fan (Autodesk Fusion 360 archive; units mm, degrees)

design "fan" references "Fan BFB1012 97x94x33"
sketch "Sketch1" plane through (0, 0, 0) normal (1, 0, 0) x axis (0, 0, -1)
sketch "Sketch2" plane through (0, 0, 0) normal (1, 0, 0) x axis (0, 0, -1)
  line L1 (-76.7953, 5.9701) -> (10.7047, 5.9701)
  line L2 (-76.7953, 30.4701) -> (-76.7953, 5.9701)
  line L3 (10.7047, 30.4701) -> (-76.7953, 30.4701)
  line L4 (10.7047, 5.9701) -> (10.7047, 30.4701)
  line L5 (-76.7953, 5.9701) -> (10.7047, 30.4701)
  line L6 (-79.5453, 30.4701) -> (13.4547, 30.4701)
  line L7 (-79.5453, 5.9701) -> (-79.5453, 30.4701)
  line L8 (13.4547, 5.9701) -> (-79.5453, 5.9701)
  line L9 (13.4547, 30.4701) -> (13.4547, 5.9701)
  line L10 (-79.5453, 5.9701) -> (13.4547, 30.4701)
  line L11 (13.4547, 5.9701) -> (-79.5453, 30.4701)
  point P10 (-33.0453, 18.2201)
  point P2 (10.7047, 5.9701)
  point P3 (-76.7953, 5.9701)
  point P5 (10.7047, 30.4701)
  point P8 (-79.5453, 5.9701)
  point P9 (13.4547, 5.9701)
  point P7 (-79.5453, 30.4701)
  horizontal L1
  vertical L2
  horizontal L3
  vertical L4
  horizontal L6
  perpendicular L6 L7
  parallel L6 L8
  parallel L7 L9
  coincident L10 P10
  coincident L11 P10
  midpoint L5 P10
  dimension "d1" distance P2 P3 = 87.5
  dimension "d2" distance P2 P5 = 24.5
  dimension "d3" distance P8 P9 = 93
  dimension "d4" distance P7 P8 = 24.5
canvas "Canvas2" sketch "Sketch2"
work_plane "WorkPlane1" sketch "Sketch2" AlongDistance -5.5
sketch "Sketch3" plane through (-5.5, 0, 0) normal (1, 0, 0) x axis (0, 0, -1)
  line L1 (13.4547, 30.4701) -> (13.4547, 5.9701)
  line L2 (-79.5453, 5.9701) -> (-79.5453, 30.4701)
  line L3 (-76.7953, 5.9701) -> (10.7047, 5.9701)
  line L4 (10.7047, 30.4701) -> (-76.7953, 30.4701)
  line L5 (-79.5453, 30.4701) -> (13.4547, 30.4701)
  line L6 (13.4547, 5.9701) -> (-79.5453, 5.9701)
loft "Loft1" sketch "Sketch2" + "Sketch3"
sketch "Sketch4" plane through (0, 0, 0) normal (1, 0, 0) x axis (0, 0, -1)
  line L1 (-76.7953, 30.4701) -> (10.7047, 30.4701)
  line L2 (-76.7953, 5.9701) -> (-76.7953, 30.4701)
  line L3 (10.7047, 5.9701) -> (-76.7953, 5.9701)
  line L4 (10.7047, 30.4701) -> (10.7047, 5.9701)
  line L5 (1.7047, 30.4701) -> (10.7047, 30.4701)
  line L6 (-16.2953, 30.4701) -> (1.7047, 30.4701)
  line L7 (-16.2953, 26.9701) -> (-16.2953, 30.4701)
  line L8 (1.7047, 26.9701) -> (-16.2953, 26.9701)
  line L9 (1.7047, 30.4701) -> (1.7047, 26.9701)
  point P2 (10.7047, 30.4701)
  point P6 (10.7047, 30.4701)
  point P7 (1.7047, 30.4701)
  point P8 (-16.2953, 30.4701)
  point P10 (1.7047, 26.9701)
  coincident P2 P6
  perpendicular L4 L5
  horizontal L6
  vertical L7
  horizontal L8
  vertical L9
  dimension "d6" distance P6 P7 = 9
  dimension "d7" distance P7 P8 = 18
  dimension "d8" distance P7 P10 = 3.5
shell "Shell1" innerThickness 2
extrude "Extrude1" cut of existing geometry blind -2
sketch "Sketch5" plane through (-5.5, 0, 0) normal (-1, 0, 0) x axis (0, 0, 1)
  line L1 (77.3092, 28.4701) -> (-11.2186, 28.4701)
  line L2 (77.3092, 7.9701) -> (77.3092, 28.4701)
  line L3 (-11.2186, 7.9701) -> (77.3092, 7.9701)
  line L4 (-11.2186, 28.4701) -> (-11.2186, 7.9701)
  line L5 (-13.4547, 30.4701) -> (79.5453, 30.4701)
  line L6 (-13.4547, 5.9701) -> (-13.4547, 30.4701)
  line L7 (79.5453, 5.9701) -> (-13.4547, 5.9701)
  line L8 (79.5453, 30.4701) -> (79.5453, 5.9701)
  line L9 (79.5453, 30.4701) -> (-13.4547, 5.9701)
  line L10 (-15.1047, 1.4701) -> (81.1953, 1.4701)
  line L11 (-15.1047, 34.9701) -> (-15.1047, 1.4701)
  line L12 (81.1953, 34.9701) -> (-15.1047, 34.9701)
  line L13 (81.1953, 1.4701) -> (81.1953, 34.9701)
  line L14 (-15.1047, 34.9701) -> (81.1953, 1.4701)
  line L15 (81.1953, 34.9701) -> (-15.1047, 1.4701)
  line L16 (-1.7047, 26.9701) -> (16.2953, 26.9701)
  line L17 (-1.7047, 30.4701) -> (-1.7047, 26.9701)
  line L18 (16.2953, 26.9701) -> (16.2953, 30.4701)
  line L19 (16.2953, 30.4701) -> (-1.7047, 30.4701)
  line L20 (-1.7047, 35.4701) -> (16.2953, 35.4701)
  line L21 (-1.7047, 25.4701) -> (-1.7047, 35.4701)
  line L22 (16.2953, 25.4701) -> (-1.7047, 25.4701)
  line L23 (16.2953, 35.4701) -> (16.2953, 25.4701)
  line L24 (-1.7047, 25.4701) -> (16.2953, 35.4701)
  line L25 (16.2953, 25.4701) -> (-1.7047, 35.4701)
  line L26 (18.2953, 37.4701) -> (18.2953, 23.4701)
  line L27 (-3.7047, 37.4701) -> (18.2953, 37.4701)
  line L28 (-3.7047, 23.4701) -> (-3.7047, 37.4701)
  line L29 (18.2953, 23.4701) -> (-3.7047, 23.4701)
  point P8 (-13.4547, 5.9701)
  point P10 (-13.4547, 5.9701)
  point P6 (79.5453, 30.4701)
  point P11 (79.5453, 30.4701)
  point P16 (33.0453, 18.2201)
  point P19 (-1.7047, 30.4701)
  point P21 (-1.7047, 30.4701)
  point P20 (16.2953, 30.4701)
  point P22 (16.2953, 30.4701)
  point P27 (7.2953, 30.4701)
  point P14 (-15.1047, 34.9701)
  point P15 (81.1953, 34.9701)
  point P13 (-15.1047, 1.4701)
  point P25 (-1.7047, 25.4701)
  point P26 (16.2953, 25.4701)
  point P24 (-1.7047, 35.4701)
  point P12 (81.1953, 1.4701)
  coincident P8 P10
  coincident P6 P11
  horizontal L10
  perpendicular L10 L11
  parallel L10 L12
  parallel L11 L13
  coincident L14 P16
  coincident L15 P16
  midpoint L9 P16
  coincident P19 P21
  coincident P20 P22
  horizontal L20
  perpendicular L20 L21
  parallel L20 L22
  parallel L21 L23
  coincident L24 P27
  coincident L25 P27
  midpoint L19 P27
  dimension "d12" distance P14 P15 = 96.3
  dimension "d13" distance P13 P14 = 33.5
  dimension "d14" distance P25 P26 = 18
  dimension "d15" distance P24 P25 = 10
  dimension "d17" = 2
  dimension "d26" distance P12 P13 = 96.3
extrude "Extrude2" add sketch "Sketch5" profile of L1 L17 L18 L21 L22 L23 L26 L28 L29 against normal blind 5.5
extrude "Extrude3" cut sketch "Sketch5" profile of L1 L5 L17 L18 L21 L23 against normal blind 5.5
extrude "Extrude4" new body sketch "Sketch5" profile of L1 L5 L6 L7 L8 L10 L11 L12 L13 L17 L18 L21 L22 L23 L26 L28 L29 along normal blind 9
extrude "Extrude5" add of existing geometry blind 2
sketch "Sketch6" plane through (-14.5, 0, 0) normal (-1, 0, 0) x axis (0, 0, 1)
  line L1 (-3.7047, 30.4701) -> (-13.4547, 30.4701)
  line L2 (-3.7047, 23.4701) -> (-3.7047, 30.4701)
  line L3 (18.2953, 23.4701) -> (-3.7047, 23.4701)
  line L4 (18.2953, 30.4701) -> (18.2953, 23.4701)
  line L5 (79.5453, 30.4701) -> (18.2953, 30.4701)
  line L6 (79.5453, 5.9701) -> (79.5453, 30.4701)
  line L7 (-13.4547, 5.9701) -> (79.5453, 5.9701)
  line L8 (-13.4547, 30.4701) -> (-13.4547, 5.9701)
  line L9 (-1.7047, 25.4701) -> (16.2953, 25.4701)
  line L10 (-1.7047, 34.9701) -> (-1.7047, 25.4701)
  line L11 (-15.1047, 34.9701) -> (-1.7047, 34.9701)
  line L12 (-15.1047, 1.4701) -> (-15.1047, 34.9701)
  line L13 (81.1953, 1.4701) -> (-15.1047, 1.4701)
  line L14 (81.1953, 36.9701) -> (81.1953, 1.4701)
  line L15 (16.2953, 36.9701) -> (81.1953, 36.9701)
  line L16 (16.2953, 25.4701) -> (16.2953, 36.9701)
  line L17 (73.1953, 36.9701) -> (81.1953, 36.9701)
  line L18 (55.1953, 33.4701) -> (73.1953, 33.4701)
  line L19 (29, 33.4701) -> (73.1953, 33.4701)
  circle C1 centre (73.1953, 33.4701) radius 2
  circle C2 centre (55.1953, 33.4701) radius 2
  circle C3 centre (45.1953, 33.4701) radius 2
  circle C4 centre (37.1953, 33.4701) radius 2
  point P16 (81.1953, 36.9701)
  point P18 (81.1953, 36.9701)
  point P19 (73.1953, 36.9701)
  point P20 (73.1953, 33.4701)
  point P21 (73.1953, 33.4701)
  point P22 (55.1953, 33.4701)
  point P23 (55.1953, 33.4701)
  point P24 (73.1953, 33.4701)
  point P26 (45.1953, 33.4701)
  point P27 (37.1953, 33.4701)
  coincident P16 P18
  coincident L15 P19
  coincident P20 P21
  horizontal L18
  coincident P22 P23
  coincident P20 P24
  coincident L19 P26
  coincident L19 P27
  dimension "d27" distance P18 P19 = 8
  dimension "d28" diameter C1 = 4
  dimension "d30" distance L5 P20 = 3
  dimension "d31" distance P21 P22 = 18
  dimension "d32" diameter C2 = 4
  dimension "d33" diameter C3 = 4
  dimension "d34" distance P23 P26 = 10
  dimension "d35" diameter C4 = 4
  dimension "d36" distance P26 P27 = 8
extrude "Extrude6" cut sketch "Sketch6" profile of C1 C2 C3 C4 against normal blind 9
work_plane "WorkPlane2" AlongDistance 10
sketch "Sketch7" plane through (-24.5, 0, 0) normal (-1, 0, 0) x axis (0, 0, 1)
component_insert "Component Insert"
position "Position1"
work_plane "WorkPlane3" AlongDistance 0
sketch "Sketch8" plane through (-14.5, 0, 0) normal (-1, 0, 0) x axis (0, 0, 1)
  line L1 (81.1953, 34.9701) -> (-15.1047, 34.9701)
  line L2 (81.1953, 1.4701) -> (81.1953, 34.9701)
  line L3 (-15.1047, 1.4701) -> (81.1953, 1.4701)
  line L4 (-15.1047, 34.9701) -> (-15.1047, 1.4701)
  line L5 (81.1953, 1.4701) -> (-15.1047, 34.9701)
  line L6 (-15.1047, 2.0928) -> (81.1953, 34.9701)
  point P3 (81.1953, 1.4701)
  point P6 (81.1953, 1.4701)
  point P2 (-15.1047, 34.9701)
  point P4 (-15.1047, 34.9701)
  point P8 (-15.1047, 34.9701)
  point P9 (81.1953, 1.4701)
  point P10 (-15.1047, 2.0928)
  horizontal L1
  vertical L2
  horizontal L3
  vertical L4
  coincident P3 P6
  coincident P2 P4
  coincident P2 P8
  coincident P3 P9
  coincident L4 P10
joint "Assemble1" alignAngle 90 alignOffsetX 0 alignOffsetY 0 alignOffsetZ 30
sketch "Sketch9" plane through (-44.5, 0, 0) normal (1, 0, 0) x axis (0, 1, 0)
  line L1 (1.7701, 4.0953) -> (1.7701, 61.9953)
  line L2 (34.6701, 4.0953) -> (1.7701, 4.0953)
  line L3 (34.6701, 61.9953) -> (34.6701, 4.0953)
  line L4 (1.7701, 61.9953) -> (34.6701, 61.9953)
  line L5 (36.6701, 63.9953) -> (36.6701, 2.0953)
  line L6 (-0.2299, 63.9953) -> (36.6701, 63.9953)
  line L7 (-0.2299, 2.0953) -> (-0.2299, 63.9953)
  line L8 (36.6701, 2.0953) -> (-0.2299, 2.0953)
  dimension "d47" = 2
extrude "Extrude8" new body sketch "Sketch9" against normal blind 10
sketch "Sketch11" plane through (0, 1.4701, 0) normal (0, -1, 0) x axis (1, 0, 0)
  line L1 (-5.5, 81.1953) -> (-5.5, -15.1047)
  line L2 (-14.5, 81.1953) -> (-5.5, 81.1953)
  line L3 (-14.5, -15.1047) -> (-14.5, 81.1953)
  line L4 (-5.5, -15.1047) -> (-14.5, -15.1047)
  line L5 (-44.5, 63.9953) -> (-44.5, 2.0953)
  line L6 (-54.5, 63.9953) -> (-44.5, 63.9953)
  line L7 (-54.5, 2.0953) -> (-54.5, 63.9953)
  line L8 (-44.5, 2.0953) -> (-54.5, 2.0953)
sketch "Sketch12" plane through (-14.5, 0, 0) normal (-1, 0, 0) x axis (0, 0, 1)
  line L1 (-13.4547, 5.9701) -> (79.5453, 5.9701)
  line L2 (-3.7047, 30.4701) -> (-13.4547, 30.4701)
  line L3 (-3.7047, 23.4701) -> (-3.7047, 30.4701)
  line L4 (18.2953, 23.4701) -> (-3.7047, 23.4701)
  line L5 (18.2953, 30.4701) -> (18.2953, 23.4701)
  line L6 (79.5453, 30.4701) -> (18.2953, 30.4701)
  line L7 (79.5453, 5.9701) -> (79.5453, 30.4701)
  line L8 (-13.4547, 5.9701) -> (79.5453, 5.9701)
  line L9 (-13.4547, 30.4701) -> (-13.4547, 5.9701)
  line L10 (-1.7047, 25.4701) -> (16.2953, 25.4701)
  line L11 (-1.7047, 34.9701) -> (-1.7047, 25.4701)
  line L12 (-15.1047, 34.9701) -> (-1.7047, 34.9701)
  line L13 (-15.1047, 1.4701) -> (-15.1047, 34.9701)
  line L14 (81.1953, 1.4701) -> (-15.1047, 1.4701)
  line L15 (81.1953, 36.9701) -> (81.1953, 1.4701)
  line L16 (16.2953, 36.9701) -> (81.1953, 36.9701)
  line L17 (16.2953, 25.4701) -> (16.2953, 36.9701)
  line L18 (-15.1047, 5.9701) -> (-13.4547, 5.9701)
  line L19 (81.1953, 5.9701) -> (79.5453, 5.9701)
  line L20 (-3.7047, 25.4701) -> (-1.7047, 25.4701)
  line L21 (18.2953, 25.4701) -> (16.2953, 25.4701)
  line L22 (18.2953, 36.9701) -> (18.2953, 30.4701)
  line L23 (-3.7047, 34.9701) -> (-3.7047, 30.4701)
  line L24 (81.1953, 30.4701) -> (79.5453, 30.4701)
  line L25 (18, 30.4701) -> (18.2953, 30.4701)
  line L26 (16.2953, 30.4701) -> (18, 30.4701)
  circle C1 centre (45.1953, 33.4701) radius 2
  circle C2 centre (55.1953, 33.4701) radius 2
  circle C3 centre (37.1953, 33.4701) radius 2
  circle C4 centre (73.1953, 33.4701) radius 2
  point P15 (-13.4547, 5.9701)
  point P24 (-13.4547, 5.9701)
  point P25 (-15.1047, 5.9701)
  point P14 (79.5453, 5.9701)
  point P26 (79.5453, 5.9701)
  point P27 (81.1953, 5.9701)
  point P17 (-1.7047, 25.4701)
  point P28 (-1.7047, 25.4701)
  point P29 (-3.7047, 25.4701)
  point P16 (16.2953, 25.4701)
  point P30 (16.2953, 25.4701)
  point P31 (18.2953, 25.4701)
  point P12 (18.2953, 30.4701)
  point P32 (18.2953, 30.4701)
  point P33 (18.2953, 36.9701)
  point P9 (-3.7047, 30.4701)
  point P34 (-3.7047, 30.4701)
  point P35 (-3.7047, 34.9701)
  point P13 (79.5453, 30.4701)
  point P36 (79.5453, 30.4701)
  point P37 (81.1953, 30.4701)
  point P39 (16.2953, 30.4701)
  coincident P15 P24
  coincident L13 P25
  perpendicular L13 L18
  coincident P14 P26
  coincident L15 P27
  perpendicular L15 L19
  coincident P17 P28
  coincident L3 P29
  perpendicular L3 L20
  coincident P16 P30
  coincident L5 P31
  perpendicular L5 L21
  coincident P12 P32
  coincident L16 P33
  perpendicular L16 L22
  coincident P9 P34
  coincident L12 P35
  perpendicular L12 L23
  coincident P13 P36
  coincident L15 P37
  perpendicular L15 L24
  perpendicular L22 L25
  coincident L17 P39
  perpendicular L17 L26
extrude "Extrude9" add sketch "Sketch12" profile of L1 L2 L7 L8 L9 L12 L13 L14 L15 L18 L19 L23 L24 along normal blind 30
sketch "Sketch13" plane through (0, 5.9701, 0) normal (0, 1, 0) x axis (-1, 0, 0)
  line L1 (5.5, -13.4547) -> (5.5, 79.5453)
  line L2 (44.5, -13.4547) -> (5.5, -13.4547)
  line L3 (44.5, 2.0953) -> (44.5, -13.4547)
  line L4 (44.5, 4.0953) -> (44.5, 2.0953)
  line L5 (44.5, 61.9953) -> (44.5, 4.0953)
  line L6 (44.5, 63.9953) -> (44.5, 61.9953)
  line L7 (44.5, 79.5453) -> (44.5, 63.9953)
  line L8 (5.5, 79.5453) -> (44.5, 79.5453)
  line L9 (5.5, 77.3092) -> (2, 75.5592)
  line L10 (44.5, 61.9953) -> (5.5, 77.3092)
  line L11 (5.5, -11.3215) -> (44.5, 4.0953)
  point P11 (5.5, 77.3092)
  point P12 (5.5, 77.3092)
  point P7 (44.5, 61.9953)
  point P13 (44.5, 61.9953)
  point P6 (44.5, 4.0953)
  point P14 (44.5, 4.0953)
  point P15 (5.5, -11.3215)
  coincident P11 P12
  coincident P7 P13
  coincident P6 P14
  coincident L1 P15
extrude "Extrude10" add sketch "Sketch13" profile of L1 L2 L3 L4 L6 L7 L8 L10 L11 along normal blind 25
work_plane "WorkPlane4"
revolve "Revolve1" AlongAngle -6
extrude "Extrude11" cut of existing geometry blind -1
sketch "Sketch14" plane through (-14.5, 0, 0) normal (-1, 0, 0) x axis (0, 0, 1)
  line L1 (79.5453, 30.4701) -> (79.5453, 30.9701)
  line L2 (81.1953, 30.4701) -> (79.5453, 30.4701)
  line L3 (81.1953, 36.9701) -> (81.1953, 30.4701)
  line L4 (16.2953, 36.9701) -> (81.1953, 36.9701)
  line L5 (16.2953, 25.4701) -> (16.2953, 36.9701)
  line L6 (-1.7047, 25.4701) -> (16.2953, 25.4701)
  line L7 (-1.7047, 34.9701) -> (-1.7047, 25.4701)
  line L8 (-3.7047, 34.9701) -> (-1.7047, 34.9701)
  line L9 (-3.7047, 30.4701) -> (-3.7047, 34.9701)
  line L10 (-3.7047, 23.4701) -> (-3.7047, 30.4701)
  line L11 (18.2953, 23.4701) -> (-3.7047, 23.4701)
  line L12 (18.2953, 30.4701) -> (18.2953, 23.4701)
  line L13 (73.7752, 30.4701) -> (18.2953, 30.4701)
  line L14 (73.7752, 30.9701) -> (73.7752, 30.4701)
  line L15 (79.5453, 30.9701) -> (73.7752, 30.9701)
  line L16 (18.2953, 36.9701) -> (18.2953, 30.4701)
  circle C1 centre (73.1953, 33.4701) radius 2
  circle C2 centre (37.1953, 33.4701) radius 2
  circle C3 centre (55.1953, 33.4701) radius 2
  circle C4 centre (45.1953, 33.4701) radius 2
  point P14 (18.2953, 30.4701)
  point P21 (18.2953, 30.4701)
  point P22 (18.2953, 36.9701)
  coincident P14 P21
  coincident L4 P22
  perpendicular L4 L16
sketch "Sketch15" plane through (0, 34.9701, 0) normal (0, 1, 0) x axis (-1, 0, 0)
  line L1 (5.5, -15.1047) -> (5.5, -1.7047)
  line L2 (44.5, -15.1047) -> (5.5, -15.1047)
  line L3 (44.5, -3.7047) -> (44.5, -15.1047)
  line L4 (14.5, -3.7047) -> (44.5, -3.7047)
  line L5 (14.5, -1.7047) -> (14.5, -3.7047)
  line L6 (5.5, -1.7047) -> (14.5, -1.7047)
  line L7 (0, -2.2047) -> (14.5, -2.2047)
  line L8 (0, -25) -> (0, -2.2047)
  line L9 (14.5, -25) -> (0, -25)
  line L10 (14.5, -2.2047) -> (14.5, -25)
  arc A1 centre (14.5, -2.2047) radius 0.5 clockwise from (14.5, -1.7047) to (14.5, -2.7047)
  point P9 (14.5, -2.7047)
  point P7 (14.5, -1.7047)
  point P8 (14.5, -1.7047)
  point P10 (14.5, -2.2047)
  point P11 (14.5, -2.2047)
  midpoint L5 P9
  coincident P7 P8
  tangent L6 A1
  horizontal L7
  vertical L8
  horizontal L9
  vertical L10
  coincident P10 P11
work_plane "WorkPlane5" AlongDistance 9.895
sketch "Sketch17" plane through (0, 0, -25) normal (0, 0, -1) x axis (-1, 0, 0)
  line L1 (14.5, 34.9701) -> (14.5, 1.4701)
sketch "Sketch18" plane through (-14.5, 0, 0) normal (-1, 0, 0) x axis (0, 0, 1)
  line L1 (18.2953, 23.4701) -> (-3.7047, 23.4701)
  line L2 (18.2953, 25.4701) -> (18.2953, 23.4701)
  line L3 (-3.7047, 25.4701) -> (18.2953, 25.4701)
  line L4 (-3.7047, 23.4701) -> (-3.7047, 25.4701)
  line L5 (79.5453, 30.4701) -> (79.5453, 30.9701)
  line L6 (81.1953, 30.4701) -> (79.5453, 30.4701)
  line L7 (81.1953, 36.9701) -> (81.1953, 30.4701)
  line L8 (16.2953, 36.9701) -> (81.1953, 36.9701)
  line L9 (16.2953, 25.4701) -> (16.2953, 36.9701)
  line L10 (-1.7047, 25.4701) -> (16.2953, 25.4701)
  line L11 (-1.7047, 34.9701) -> (-1.7047, 25.4701)
  line L12 (-3.7047, 34.9701) -> (-1.7047, 34.9701)
  line L13 (-3.7047, 30.4701) -> (-3.7047, 34.9701)
  line L14 (-3.7047, 23.4701) -> (-3.7047, 30.4701)
  line L15 (18.2953, 23.4701) -> (-3.7047, 23.4701)
  line L16 (18.2953, 30.4701) -> (18.2953, 23.4701)
  line L17 (73.7752, 30.4701) -> (18.2953, 30.4701)
  line L18 (73.7752, 30.9701) -> (73.7752, 30.4701)
  line L19 (79.5453, 30.9701) -> (73.7752, 30.9701)
  line L20 (16.2953, 23.4701) -> (18.2953, 23.4701)
  line L21 (16.2953, 36.9701) -> (16.2953, 23.4701)
  line L22 (18.2953, 36.9701) -> (16.2953, 36.9701)
  line L23 (18.2953, 23.4701) -> (18.2953, 36.9701)
  circle C1 centre (73.1953, 33.4701) radius 2
  circle C2 centre (37.1953, 33.4701) radius 2
  circle C3 centre (55.1953, 33.4701) radius 2
  circle C4 centre (45.1953, 33.4701) radius 2
  point P2 (-3.7047, 23.4701)
  point P6 (-3.7047, 23.4701)
  point P14 (16.2953, 36.9701)
  point P31 (16.2953, 36.9701)
  point P5 (18.2953, 23.4701)
  point P29 (18.2953, 23.4701)
  horizontal L1
  vertical L2
  horizontal L3
  vertical L4
  coincident P2 P6
  horizontal L20
  vertical L21
  horizontal L22
  vertical L23
  coincident P14 P31
  coincident P5 P29
sketch "Sketch19" plane through (-44.5, 0, 0) normal (1, 0, 0) x axis (0, 0, -1)
  line L1 (-2.0953, 30.9701) -> (-4.0953, 30.9701)
  line L2 (-2.0953, 36.6701) -> (-2.0953, 30.9701)
  line L3 (-63.9953, 36.6701) -> (-2.0953, 36.6701)
  line L4 (-63.9953, 30.9701) -> (-63.9953, 36.6701)
  line L5 (-61.9953, 30.9701) -> (-63.9953, 30.9701)
  line L6 (-61.9953, 34.6701) -> (-61.9953, 30.9701)
  line L7 (-4.0953, 34.6701) -> (-61.9953, 34.6701)
  line L8 (-4.0953, 30.9701) -> (-4.0953, 34.6701)
loft "Loft2" sketch "Sketch19" + "Sketch18"
sketch "Sketch20" plane through (0, 34.9701, 0) normal (0, 1, 0) x axis (-1, 0, 0)
  line L1 (5.5, -15.1047) -> (5.5, -1.7047)
  line L2 (44.5, -15.1047) -> (5.5, -15.1047)
  line L3 (44.5, -3.7047) -> (44.5, -15.1047)
  line L4 (14.5, -3.7047) -> (44.5, -3.7047)
  line L5 (14.5, -1.7047) -> (14.5, -3.7047)
  line L6 (5.5, -1.7047) -> (14.5, -1.7047)
  line L7 (34.5975, 0.1808) -> (44.5, 2.0953)
  line L8 (24.7683, -3.7047) -> (34.5975, 0.1808)
  line L9 (44.5, -3.7047) -> (24.7683, -3.7047)
  line L10 (44.5, 2.0953) -> (44.5, -3.7047)
  line L11 (5.5, -15.1047) -> (44.5, 2.0953)
  line L12 (44.5, -15.1047) -> (5.5, -15.1047)
  line L13 (44.5, 1) -> (44.5, 2.0953)
  point P8 (44.5, 2.0953)
  point P12 (44.5, 2.0953)
  point P3 (5.5, -15.1047)
  point P13 (5.5, -15.1047)
  point P4 (44.5, -15.1047)
  point P14 (44.5, -15.1047)
  point P15 (44.5, 2.0953)
  point P16 (44.5, 1)
  coincident P8 P12
  coincident P3 P13
  coincident P4 P14
  coincident P8 P15
  coincident L10 P16
extrude "Extrude12" cut sketch "Sketch20" profile of L2 L3 L4 L9 L10 L11 L12 L13 against normal blind 35
sketch "Sketch21" plane through (0, 34.9701, 0) normal (0, 1, 0) x axis (-1, 0, 0)
  line L1 (31.3488, -3.7047) -> (5.5, -15.1047)
  line L2 (14.5, -1.7047) -> (14.5, -3.7047)
  line L3 (5.5, -1.7047) -> (14.5, -1.7047)
  line L4 (5.5, -15.1047) -> (5.5, -1.7047)
delete_face "DeleteFace1"
extrude "Extrude13" new body of existing geometry blind 2
loft "Loft3"
delete_face "DeleteFace2"
delete_face "DeleteFace3"
sketch "Sketch22" plane through (-1.4411, 8.6466, 0) normal (0.1644, -0.9864, 0) x axis (0.9864, 0.1644, 0)
work_plane "WorkPlane6" AlongDistance 0
sketch "Sketch23" plane through (0, 36.9701, 0) normal (0, 1, 0) x axis (1, 0, 0)
  line L1 (-5.5, -77.3092) -> (-44.5, -61.9953)
  line L2 (-5.5, -77.3092) -> (-2, -75.5592)
  line L3 (-2, -75.5592) -> (0, -75.5592)
  line L4 (0, -75.5592) -> (-2, -75.5592)
  line L5 (-5.5, -79.5453) -> (0, -76.7953)
  line L6 (-54.5, -63.9953) -> (-44.5, -63.9953)
  line L7 (-54.5, -61.9953) -> (-43.5, -61.9953)
  line L8 (-44.5, -81.1953) -> (-44.5, -63.9953)
  line L9 (-5.5, -79.5453) -> (-44.5, -63.9953)
  line L10 (-5.5728, -63.9953) -> (-44.5, -63.9953)
  line L11 (-5.5728, -81.1953) -> (-5.5728, -63.9953)
  line L12 (-44.5, -81.1953) -> (-5.5728, -81.1953)
  line L13 (-44.5, -63.9953) -> (-44.5, -81.1953)
  point P14 (-44.5, -63.9953)
  point P16 (-44.5, -63.9953)
  point P9 (-5.5, -79.5453)
  point P17 (-5.5, -79.5453)
  point P18 (-44.5, -63.9953)
  coincident P14 P16
  coincident P9 P17
  horizontal L10
  vertical L11
  horizontal L12
  vertical L13
  coincident P14 P18
extrude "Extrude14" cut sketch "Sketch23" profile of L8 L9 L11 L12 L13 against normal blind 37
delete_face "DeleteFace4"
sketch "Sketch24" plane through (-14.5, 0, 0) normal (-1, 0, 0) x axis (0, 0, 1)
  line L1 (75.9568, 36.9701) -> (75.9568, 30.9701)
  line L2 (16.2953, 36.9701) -> (75.9568, 36.9701)
  line L3 (16.2953, 25.4701) -> (16.2953, 36.9701)
  line L4 (73.7752, 25.4701) -> (16.2953, 25.4701)
  line L5 (73.7752, 30.9701) -> (73.7752, 25.4701)
  line L6 (75.9568, 30.9701) -> (73.7752, 30.9701)
  circle C1 centre (73.1953, 33.4701) radius 2
  circle C2 centre (37.1953, 33.4701) radius 2
  circle C3 centre (55.1953, 33.4701) radius 2
  circle C4 centre (45.1953, 33.4701) radius 2
  circle C5 centre (37.1953, 33.4701) radius 2
  circle C6 centre (45.1953, 33.4701) radius 2
  circle C7 centre (55.1953, 33.4701) radius 2
  circle C8 centre (73.1953, 33.4701) radius 2
  circle C9 centre (73.1953, 33.4701) radius 2
extrude "Extrude15" cut sketch "Sketch24" profile of C1 C2 C3 C4 C5 C6 C7 C8 C9 along normal blind 68
sketch "Sketch25" plane through (-54.5, 0, 0) normal (-1, 0, 0) x axis (0, 0, 1)
  line L1 (63.9953, 36.6701) -> (63.9953, -0.2299)
  line L2 (2.0953, 36.6701) -> (63.9953, 36.6701)
  line L3 (2.0953, -0.2299) -> (2.0953, 36.6701)
  line L4 (63.9953, -0.2299) -> (2.0953, -0.2299)
  line L5 (53.5953, 34.6701) -> (46.7953, 34.6701)
  line L6 (61.9953, 34.6701) -> (56.7953, 34.6701)
  line L7 (61.9953, 1.7701) -> (61.9953, 34.6701)
  line L8 (4.0953, 1.7701) -> (61.9953, 1.7701)
  line L9 (4.0953, 34.6701) -> (4.0953, 1.7701)
  line L10 (35.5953, 34.6701) -> (4.0953, 34.6701)
  line L11 (43.5953, 34.6701) -> (38.7953, 34.6701)
  line L12 (4.0953, 36.6701) -> (2.0953, 36.6701)
  line L13 (4.0953, -0.2299) -> (4.0953, 36.6701)
  line L14 (2.0953, -0.2299) -> (4.0953, -0.2299)
  line L15 (2.0953, 36.6701) -> (2.0953, -0.2299)
  line L16 (63.9953, 34.6701) -> (61.9953, 34.6701)
  line L17 (63.9953, 1.7701) -> (61.9953, 1.7701)
  arc A1 centre (45.1953, 33.4701) radius 2 clockwise from (43.5953, 34.6701) to (46.7953, 34.6701)
  arc A2 centre (55.1953, 33.4701) radius 2 clockwise from (53.5953, 34.6701) to (56.7953, 34.6701)
  arc A3 centre (37.1953, 33.4701) radius 2 clockwise from (35.5953, 34.6701) to (38.7953, 34.6701)
  point P21 (4.0953, -0.2299)
  point P4 (2.0953, 36.6701)
  point P19 (2.0953, 36.6701)
  point P12 (61.9953, 34.6701)
  point P23 (61.9953, 34.6701)
  point P24 (63.9953, 34.6701)
  point P13 (61.9953, 1.7701)
  point P25 (61.9953, 1.7701)
  point P26 (63.9953, 1.7701)
  horizontal L12
  vertical L13
  horizontal L14
  vertical L15
  coincident L4 P21
  coincident P4 P19
  coincident P12 P23
  coincident L1 P24
  perpendicular L1 L16
  coincident P13 P25
  coincident L1 P26
  perpendicular L1 L17
sketch "Sketch27" plane through (-54.5, 0, 0) normal (-1, 0, 0) x axis (0, 0, 1)
  line L1 (63.9953, 36.6701) -> (63.9953, -0.2299)
  line L2 (2.0953, 36.6701) -> (63.9953, 36.6701)
  line L3 (2.0953, -0.2299) -> (2.0953, 36.6701)
  line L4 (63.9953, -0.2299) -> (2.0953, -0.2299)
  line L5 (53.5953, 34.6701) -> (46.7953, 34.6701)
  line L6 (61.9953, 34.6701) -> (56.7953, 34.6701)
  line L7 (61.9953, 1.7701) -> (61.9953, 34.6701)
  line L8 (4.0953, 1.7701) -> (61.9953, 1.7701)
  line L9 (4.0953, 34.6701) -> (4.0953, 1.7701)
  line L10 (35.5953, 34.6701) -> (4.0953, 34.6701)
  line L11 (43.5953, 34.6701) -> (38.7953, 34.6701)
  line L12 (4.0953, 36.6701) -> (2.0953, 36.6701)
  line L13 (4.0953, -0.2299) -> (4.0953, 36.6701)
  line L14 (2.0953, -0.2299) -> (4.0953, -0.2299)
  line L15 (2.0953, 36.6701) -> (2.0953, -0.2299)
  line L16 (63.9953, 36.6701) -> (61.9953, 36.6701)
  line L17 (63.9953, -0.2299) -> (63.9953, 36.6701)
  line L18 (61.9953, -0.2299) -> (63.9953, -0.2299)
  line L19 (61.9953, 36.6701) -> (61.9953, -0.2299)
  arc A1 centre (45.1953, 33.4701) radius 2 clockwise from (43.5953, 34.6701) to (46.7953, 34.6701)
  arc A2 centre (55.1953, 33.4701) radius 2 clockwise from (53.5953, 34.6701) to (56.7953, 34.6701)
  arc A3 centre (37.1953, 33.4701) radius 2 clockwise from (35.5953, 34.6701) to (38.7953, 34.6701)
  point P21 (4.0953, -0.2299)
  point P4 (2.0953, 36.6701)
  point P19 (2.0953, 36.6701)
  point P2 (63.9953, -0.2299)
  point P25 (63.9953, -0.2299)
  point P23 (61.9953, 36.6701)
  horizontal L12
  vertical L13
  horizontal L14
  vertical L15
  coincident L4 P21
  coincident P4 P19
  horizontal L16
  vertical L17
  horizontal L18
  vertical L19
  coincident P2 P25
  coincident L2 P23
extrude "Extrude17" new body sketch "Sketch27" profile of L2 L4 A1 L5 A2 L6 L8 L10 A3 L11 L13 L19 along normal blind 4
extrude "Extrude18" add of existing geometry blind 35
extrude "Extrude19" add of existing geometry blind 33
work_plane "WorkPlane7"
sketch "Sketch28" plane through (0, 18.2201, 0) normal (0, 1, 0) x axis (1, 0, 0)
  line L1 (-31.3488, 3.7047) -> (-5.5, 15.1047)
  line L2 (-44.5, 30.9047) -> (-44.5, -63.9953)
  line L3 (-5.5, 15.1047) -> (-44.5, -2.0953)
  line L4 (-44.5, 30.9047) -> (-5.5, 15.1047)
  point P2 (-5.5, 15.1047)
  point P8 (-5.5, 15.1047)
  point P5 (-44.5, 30.9047)
  point P9 (-44.5, 30.9047)
  coincident P2 P8
  coincident P5 P9
step "Rib" Thickness 2 DraftAngle 0 FilletRadius 0
sketch "Sketch29" plane through (0, 36.6701, 0) normal (0, 1, 0) x axis (-1, 0, 0)
  line L1 (44.5, 63.9953) -> (54.5, 63.9953)
  line L2 (44.5, 26.2258) -> (44.5, 63.9953)
  line L3 (44.5, 6.2919) -> (44.5, 26.2258)
  line L4 (44.5, 2.0953) -> (44.5, 6.2919)
  line L5 (44.5, -30.9047) -> (44.5, 2.0953)
  line L6 (58.5, -30.9047) -> (44.5, -30.9047)
  line L7 (58.5, 61.9953) -> (58.5, -30.9047)
  line L8 (54.5, 61.9953) -> (58.5, 61.9953)
  line L9 (54.5, 63.9953) -> (54.5, 61.9953)
  line L10 (61.1956, 61.9953) -> (61.1956, 63.6825)
  line L11 (44.5, 61.9953) -> (61.1956, 61.9953)
  line L12 (44.5, 4.0953) -> (44.5, 61.9953)
  line L13 (55.4749, 4.0953) -> (44.5, 4.0953)
  line L14 (54.8804, -1.6597) -> (56.4595, -0.7893)
  line L15 (59.9712, -10.688) -> (58.4862, -11.4319)
  line L16 (128.9069, -22.2087) -> (127.4495, -20.9634)
  line L17 (132.5577, -15.6424) -> (134.0063, -17.0355)
  line L18 (124.7757, 51.9385) -> (123.9133, 50.5613)
  line L19 (115.6848, 56.4952) -> (116.3861, 57.5937)
  line L20 (71.4904, 61.9953) -> (94.5, 61.9953)
  line L21 (71.4904, 63.6825) -> (71.4904, 61.9953)
  line L22 (61.1956, 63.6825) -> (71.4904, 63.6825)
  arc A1 centre (109.4237, 12.4281) radius 54.5885 clockwise from (56.4595, -0.7893) to (55.4749, 4.0953)
  arc A2 centre (91.7545, 6.3949) radius 37.7436 clockwise from (58.4862, -11.4319) to (54.8804, -1.6597)
  arc A3 centre (109.4237, 12.4281) radius 54.5885 clockwise from (62.501, -15.4675) to (59.9712, -10.688)
  arc A4 centre (49.2314, -7.7138) radius 15.3689 clockwise from (62.501, -15.4675) to (59.5327, -19.1193)
  arc A5 centre (62.5, -22.4047) radius 4.4271 clockwise from (65.8526, -25.2958) to (59.5327, -19.1193)
  arc A6 centre (69.3534, -28.3147) radius 4.6227 clockwise from (65.8526, -25.2958) to (70.8097, -23.9275)
  arc A7 centre (97.2681, 13.1239) radius 45.5286 clockwise from (127.4495, -20.9634) to (70.8097, -23.9275)
  arc A8 centre (98.7927, 12.5752) radius 46.0086 clockwise from (134.0063, -17.0355) to (128.9069, -22.2087)
  arc A9 centre (97.2681, 13.1239) radius 45.5286 clockwise from (133.1988, 41.0853) to (132.5577, -15.6424)
  arc A10 centre (139.5557, 39.2869) radius 6.6064 clockwise from (133.1988, 41.0853) to (135.9531, 44.8245)
  arc A11 centre (133.5, 48.5953) radius 4.4985 clockwise from (130.3613, 51.8179) to (135.9531, 44.8245)
  arc A12 centre (117.026, 65.5097) radius 19.1127 clockwise from (130.3613, 51.8179) to (125.9254, 48.5953)
  arc A13 centre (94.5, 18.4462) radius 43.5491 clockwise from (123.9133, 50.5613) to (125.9254, 48.5953)
  arc A14 centre (65.7082, -26.6386) radius 98.3023 clockwise from (116.3861, 57.5937) to (124.7757, 51.9385)
  arc A15 centre (94.5, 18.4462) radius 43.5491 clockwise from (94.5, 61.9953) to (115.6848, 56.4952)
  circle C1 centre (62.5, -22.4047) radius 2.25
  circle C2 centre (133.5, 48.5953) radius 2.25
  circle C3 centre (94.5, 9.5953) radius 29.45
extrude "Extrude20" cut sketch "Sketch29" profile of L7 C1 against normal blind 36.9
sketch "Sketch30" plane through (0, 36.6701, 0) normal (0, 1, 0) x axis (-1, 0, 0)
  line L1 (44.5, 63.9953) -> (54.5, 63.9953)
  line L2 (44.5, 26.2258) -> (44.5, 63.9953)
  line L3 (44.5, 6.2919) -> (44.5, 26.2258)
  line L4 (44.5, 2.0953) -> (44.5, 6.2919)
  line L5 (44.5, -30.9047) -> (44.5, 2.0953)
  line L6 (58.5, -30.9047) -> (44.5, -30.9047)
  line L7 (58.5, 61.9953) -> (58.5, -30.9047)
  line L8 (54.5, 61.9953) -> (58.5, 61.9953)
  line L9 (54.5, 63.9953) -> (54.5, 61.9953)
  line L10 (58.5, -7) -> (58.5, -9.7729)
  line L11 (58.5, -30.9047) -> (58.5, -30.5939)
  circle C1 centre (62.5, -22.4047) radius 2.25
  circle C2 centre (62.5, -22.4047) radius 2.25
  circle C3 centre (62.5, -22.4047) radius 3.25
  arc A1 centre (62.5, -22.4047) radius 5.25 clockwise from (64.0849, -17.3996) to (62.2, -27.6461)
  arc A2 centre (66.5, -9.7729) radius 8 clockwise from (64.0849, -17.3996) to (58.5, -9.7729)
  arc A3 centre (62.5, -22.4047) radius 5.25 clockwise from (58.5, -19.0043) to (61.8636, -27.616)
  arc A4 centre (61.5, -30.5939) radius 3 clockwise from (58.5, -30.5939) to (61.8636, -27.616)
  point P14 (58.5, -7)
  point P18 (62.2, -27.6461)
  point P19 (58.5, -30.9047)
  point P21 (58.5, -30.9047)
  point P22 (58.5, -19.0043)
  coincident L7 P14
  concentric C3 A1
  tangent A1 A2
  tangent L10 A2
  concentric A1 A3
  coincident P18 A3
  coincident P19 P21
  coincident L7 P22
  tangent A3 A4
  tangent L11 A4
  dimension "d81" = 1
  dimension "d85" radius A2 = 8
  dimension "d87" radius A4 = 3
extrude "Extrude21" new body sketch "Sketch30" profile of L7 C3 A1 A2 A3 A4 against normal blind 2
work_plane "WorkPlane8"
mirror "Mirror1" mirrorStitchTolerance 0.1
combine "Combine1"
combine "Combine2"
fillet "Fillet2" radius 9
fillet "Fillet3" radius 9
fillet "Fillet4" radius 3.5
fillet "Fillet5" radius 17
fillet "Fillet6" radius 2
fillet "Fillet7" radius 4.5
fillet "Fillet8" radius 1
fillet "Fillet9" radius 14.5
sketch "Sketch32" plane through (6.5719, 17.6033, 0) normal (0.3498, 0.9368, 0) x axis (0, 0, -1)
  line L1 (-26.2258, 54.515) -> (1.7047, 22.4925)
  line L2 (-63.9953, 54.515) -> (-26.2258, 54.515)
  line L3 (-68.9726, 38.2178) -> (-63.9953, 54.515)
  line L4 (-67.9905, 38.2178) -> (-68.9726, 38.2178)
  line L5 (-73.7752, 22.4925) -> (-67.9905, 38.2178)
  line L6 (-18.2953, 22.4925) -> (-73.7752, 22.4925)
  line L7 (-16.2953, 22.4925) -> (-18.2953, 22.4925)
  line L8 (1.7047, 22.4925) -> (-16.2953, 22.4925)
  closed curve K1 centre (-45.1953, 45.3657)
  closed curve K2 centre (-55.1953, 45.3657)
  closed curve K3 centre (-37.1953, 45.3657)
extrude "Extrude24" new body sketch "Sketch32" along normal blind 2
fillet "Fillet10" radius 8
move "Move1"
work_plane "WorkPlane9"
sketch "Sketch33" plane through (0.5839, 0, 32.4681) normal (0.018, 0, 0.9998) x axis (-0.9998, 0, 0.018)
  line L1 (15.8243, -25.4701) -> (30.45, -30.9701)
  line L2 (59.5118, -34.6701) -> (45.5141, -34.6701)
  line L3 (45.4565, -34.6701) -> (59.4543, -34.6701)
  line L4 (15.8243, -30.9701) -> (15.8243, -25.4701)
  line L5 (30.45, -30.9701) -> (15.8243, -25.4701)
  line L6 (15.8243, -30.9701) -> (30.45, -30.9701)
  line L7 (15.8243, -25.4701) -> (15.8243, -30.9701)
  line L8 (15.8635, -36.9701) -> (15.8635, -30.9701)
  line L9 (14.7907, -36.9701) -> (15.8635, -36.9701)
  line L10 (14.7907, -25.4701) -> (14.7907, -36.9701)
  line L11 (14.8266, -25.4701) -> (14.7907, -25.4701)
  line L12 (15.8243, -25.4701) -> (14.8266, -25.4701)
  line L13 (15.8243, -30.9701) -> (15.8243, -25.4701)
  line L14 (15.8635, -30.9701) -> (15.8243, -30.9701)
  line L15 (23, -29.5028) -> (14.7907, -29.5028)
  line L16 (23, -26.5) -> (23, -29.5028)
  line L17 (14.7907, -26.5) -> (23, -26.5)
  line L18 (14.7907, -29.5028) -> (14.7907, -26.5)
  closed curve K1 centre (36.9153, -33.4701)
  closed curve K2 centre (42.2715, -33.4701)
  closed curve K3 centre (59.483, -33.4701)
  closed curve K4 centre (15.8138, -33.4701)
  closed curve K5 centre (15.1665, -33.4701)
  closed curve K6 centre (15.4902, -33.4701)
  closed curve K7 centre (15.3103, -33.4701)
  point P26 (14.7907, -29.5028)
  horizontal L15
  vertical L16
  horizontal L17
  vertical L18
  coincident L10 P26
delete_face "DeleteFace5"
extrude "Extrude25" add sketch "Sketch33" profile of L1 L4 L5 L7 L10 L13 L15 L16 L17 L18 along normal blind 45
extrude "Extrude26" add of existing geometry blind 5
extrude "Extrude27" add sketch "Sketch33" profile of L1 L4 L5 L7 L10 L13 L15 L16 L17 L18 against normal blind 16
extrude "Extrude28" add of existing geometry blind 2
sketch "Sketch34" plane through (0, 26.5, 0) normal (0, -1, 0) x axis (1, 0, 0)
  line L1 (-17.2586, 16.7864) -> (-17.2586, 50.6182)
  line L2 (-16.5, 16.7728) -> (-17.2586, 16.7864)
  line L3 (-14.464, 18.2953) -> (-16.5, 18.2953)
  line L4 (-13.4589, 74.1841) -> (-14.464, 18.2953)
  line L5 (-17.2586, 72.692) -> (-13.4589, 74.1841)
  line L6 (-17.6157, 52.837) -> (-17.2586, 72.692)
  curve K1 (-17.6157, 52.837) -> (-17.2586, 50.6182)
  line L7 (-16.5, 18.2953) -> (-16.5, 16.7728)
  line L8 (-5.5, -11.3215) -> (-44.5, 4.0953)
  line L9 (-24.7683, -3.7047) -> (-5.5, -11.3215)
  line L10 (-24.7683, -3.7047) -> (-25.63, -3.3641)
  line L11 (-44.5, 4.0953) -> (-25.63, -3.3641)
  line L12 (-21.728, 70.9371) -> (-26.7643, 68.9595)
  line L13 (-17.2586, 72.692) -> (-21.728, 70.9371)
  line L14 (-13.4589, 74.1841) -> (-17.2586, 72.692)
  line L15 (-5.5, 77.3092) -> (-13.4589, 74.1841)
  line L16 (-44.5, 61.9953) -> (-5.5, 77.3092)
  line L17 (-43.4913, 62.3914) -> (-44.5, 61.9953)
  line L18 (-31.8458, 66.9642) -> (-43.4913, 62.3914)
  line L19 (-27.8929, 68.5163) -> (-31.8458, 66.9642)
  line L20 (-26.7643, 68.9595) -> (-27.8929, 68.5163)
  line L21 (-4.5, -10.7186) -> (-2, -9.4686)
  line L22 (-5.5, -11.2186) -> (-4.5, -10.7186)
  line L23 (-2, -9.4686) -> (-5.5, -11.2186)
  line L24 (-2, -9.4686) -> (0, -9.4686)
  line L25 (0, -9.4686) -> (-2, -9.4686)
  line L26 (-5.5, 77.3092) -> (-2, 75.5592)
  line L27 (-2, 75.5592) -> (-5.5, 77.3092)
  line L28 (-2, 75.5592) -> (0, 75.5592)
  line L29 (0, 75.5592) -> (-2, 75.5592)
  line L30 (-44.5, 61.9953) -> (-44.5, 4.0953)
  line L31 (0, 75.5592) -> (0, -9.4686)
  point P10 (-44.5, 4.0953)
  point P32 (-44.5, 4.0953)
  point P19 (-44.5, 61.9953)
  point P33 (-44.5, 61.9953)
  point P26 (0, -9.4686)
  point P34 (0, -9.4686)
  point P30 (0, 75.5592)
  point P35 (0, 75.5592)
  coincident P10 P32
  coincident P19 P33
  coincident P26 P34
  coincident P30 P35
delete_face "DeleteFace6"
draft "Draft1" Angle1 3.8 Angle2 0
delete_face "DeleteFace7"
sketch "Sketch36" plane through (-16.5, 0, 0) normal (-1, 0, 0) x axis (0, 0, 1)
  line L1 (18.2953, 26.5) -> (18.2953, 25.4701)
  line L2 (16.7728, 26.5) -> (18.2953, 26.5)
  line L3 (16.7368, 26.5) -> (16.7728, 26.5)
  line L4 (16.7368, 29.5028) -> (16.7368, 26.5)
  line L5 (16.7728, 29.5028) -> (16.7368, 29.5028)
  line L6 (72.9899, 29.5028) -> (16.7728, 29.5028)
  line L7 (72.9899, 30.9701) -> (72.9899, 29.5028)
  line L8 (75.1594, 30.9701) -> (72.9899, 30.9701)
  line L9 (75.9568, 30.9701) -> (75.1594, 30.9701)
  line L10 (75.9568, 36.9701) -> (75.9568, 30.9701)
  line L11 (16.2953, 36.9701) -> (75.9568, 36.9701)
  line L12 (16.2953, 26.2168) -> (16.2953, 36.9701)
  line L13 (6.4315, 26.2168) -> (16.2953, 26.2168)
  line L14 (6.4315, 26.2168) -> (-1.6768, 24.21)
  line L15 (16.2953, 23.4701) -> (0.7953, 23.4701)
  line L16 (18.2953, 26.2168) -> (16.2953, 26.2168)
  circle C1 centre (45.1953, 33.4701) radius 2
  circle C2 centre (55.1953, 33.4701) radius 2
  circle C3 centre (37.1953, 33.4701) radius 2
  circle C4 centre (73.1953, 33.4701) radius 2
  arc A1 centre (0.7953, 27.9701) radius 4.5 clockwise from (0.7953, 23.4701) to (-1.6768, 24.21)
  arc A2 centre (16.2953, 25.4701) radius 2 clockwise from (18.2953, 25.4701) to (16.2953, 23.4701)
  point P18 (16.2953, 26.2168)
  point P25 (16.2953, 26.2168)
  point P26 (18.2953, 26.2168)
  coincident P18 P25
  coincident L1 P26
  perpendicular L1 L16
extrude "Extrude29" add of existing geometry blind 1
extrude "Extrude30" add of existing geometry blind 1.15
extrude "Extrude32" add of existing geometry blind 0.5
extrude "Extrude33" add of existing geometry blind 0.1
sketch "Sketch37" plane through (0, 1.7701, 0) normal (0, 1, 0) x axis (-1, 0, 0)
  line L1 (58.5, 61.9953) -> (58.5, -9.7729)
  line L2 (54.5, 61.9953) -> (54.5, 63.9953)
  line L3 (43.5, 61.9953) -> (54.5, 61.9953)
  line L4 (43.5, 4.0953) -> (43.5, 61.9953)
  line L5 (44.2732, 4.0953) -> (43.5, 4.0953)
  curve K1 (54.5, -9.7693) -> (44.2732, 4.0953)
  line L6 (54.5, -30.8137) -> (54.5, -9.7693)
  line L7 (54.5, -9.7693) -> (58.5, -9.7729)
  arc A1 centre (53.2236, -21.9047) radius 9 clockwise from (59.4309, -28.4216) to (54.5, -30.8137)
  arc A2 centre (61.5, -30.5939) radius 3 clockwise from (59.4309, -28.4216) to (61.8636, -27.616)
  arc A3 centre (62.5, -22.4047) radius 5.25 clockwise from (64.0849, -17.3996) to (61.8636, -27.616)
  arc A4 centre (66.5, -9.7729) radius 8 clockwise from (64.0849, -17.3996) to (58.5, -9.7729)
  arc A5 centre (64.0366, 78.0685) radius 17 clockwise from (58.5, 61.9953) to (54.5, 63.9953)
  circle C1 centre (62.5, -22.4047) radius 3.25
  point P9 (58.5, -9.7729)
  point P19 (58.5, -9.7729)
  point P18 (54.5, -9.7693)
  point P20 (54.5, -9.7693)
  coincident P9 P19
  coincident P18 P20
extrude "Extrude34" add sketch "Sketch37" profile of A1 A2 A3 A4 L6 C1 L7 along normal blind 3
sketch "Sketch38" plane through (0, 36.6701, 0) normal (0, 1, 0) x axis (-1, 0, 0)
  line L1 (53.2236, -30.9047) -> (48, -30.9047)
  line L2 (58.5, 61.9953) -> (58.5, -9.7729)
  line L3 (44.5, 63.9953) -> (54.5, 63.9953)
  line L4 (44.5, 26.2258) -> (44.5, 63.9953)
  line L5 (44.5, 6.2919) -> (44.5, 26.2258)
  line L6 (44.5, -11.7103) -> (44.5, 6.2919)
  line L7 (44.5, -27.4047) -> (44.5, -11.7103)
  line L8 (44.5, -9.7729) -> (58.5, -9.7729)
  arc A1 centre (48, -27.4047) radius 3.5 clockwise from (48, -30.9047) to (44.5, -27.4047)
  arc A2 centre (53.2236, -21.9047) radius 9 clockwise from (59.4309, -28.4216) to (53.2236, -30.9047)
  arc A3 centre (61.5, -30.5939) radius 3 clockwise from (59.4309, -28.4216) to (61.8636, -27.616)
  arc A4 centre (62.5, -22.4047) radius 5.25 clockwise from (64.0849, -17.3996) to (61.8636, -27.616)
  arc A5 centre (66.5, -9.7729) radius 8 clockwise from (64.0849, -17.3996) to (58.5, -9.7729)
  arc A6 centre (64.0366, 78.0685) radius 17 clockwise from (58.5, 61.9953) to (54.5, 63.9953)
  circle C1 centre (62.5, -22.4047) radius 3.25
  point P12 (58.5, -9.7729)
  point P21 (58.5, -9.7729)
  point P22 (44.5, -9.7729)
  coincident P12 P21
  coincident L6 P22
  perpendicular L6 L8
extrude "Extrude35" add sketch "Sketch38" profile of A1 L1 A2 A3 A4 A5 L6 L7 C1 L8 along normal blind 1
sketch "Sketch39" plane through (0, 34.6701, 0) normal (0, -1, 0) x axis (1, 0, 0)
  line L1 (-54.5, -9.6887) -> (-54.5, -30.8137)
  line L2 (-44.5, 35.5953) -> (-44.5, 4.0953)
  line L3 (-58.5, 35.5953) -> (-44.5, 35.5953)
  line L4 (-58.5, -9.7729) -> (-58.5, 35.5953)
  line L5 (-44.5, -9.7729) -> (-58.5, -9.7729)
  arc A1 centre (-53.2236, -21.9047) radius 9 clockwise from (-54.5, -30.8137) to (-59.4309, -28.4216)
  arc A2 centre (-40, -9.6887) radius 14.5 clockwise from (-54.5, -9.6887) to (-44.5, 4.0953)
  arc A3 centre (-66.5, -9.7729) radius 8 clockwise from (-58.5, -9.7729) to (-64.0849, -17.3996)
  arc A4 centre (-62.5, -22.4047) radius 5.25 clockwise from (-61.8636, -27.616) to (-64.0849, -17.3996)
  arc A5 centre (-61.5, -30.5939) radius 3 clockwise from (-61.8636, -27.616) to (-59.4309, -28.4216)
  circle C1 centre (-62.5, -22.4047) radius 3.25
extrude "Extrude36" cut sketch "Sketch39" profile of A1 L1 A3 A4 A5 C1 L5 against normal blind 1
fillet "Fillet11" radius 4.25
fillet "Fillet12" radius 9.5
fillet "Fillet13" radius 9.75
fillet "Fillet14" radius 7.5
fillet "Fillet15" radius 14.5
extrude "Extrude37" add of existing geometry blind 0.545
extrude "Extrude38" add of existing geometry blind 3
fillet "Fillet16" radius 15.5
fillet "Fillet17" radius 13
chamfer "Chamfer1" distance 1.5
fillet "Fillet18" radius 3
fillet "Fillet19" radius 0.75
extrude "Extrude39" add of existing geometry blind 0.2
extrude "Extrude40" add of existing geometry blind 0.8
sketch "Sketch40" plane through (0, 19.2201, 0) normal (0, 1, 0) x axis (-1, 0, 0)
  line L1 (17.1248, -19.8142) -> (35.5, -11.7103)
  line L2 (35.5, -27.2585) -> (17.1248, -19.8142)
  line L3 (35.5, -11.7103) -> (35.5, -27.2585)
  circle C1 centre (30.3199, -19.7652) radius 2
  point P5 (30.3199, -19.7652)
  dimension "d171" diameter C1 = 4
  dimension "d172" distance L2 P5 = 5
extrude "Extrude41" cut sketch "Sketch40" profile of C1 against normal blind 2
fillet "Fillet20" radius 0.95
fillet "Fillet21" radius 0.45
fillet "Fillet22" radius 1.75
sketch "Sketch41" plane through (5.5789, 18.6282, 0) normal (-0.2869, -0.958, 0) x axis (0, 0, 1)
  line L1 (61.9953, 29.5757) -> (16.7893, 29.5757)
  line L2 (61.9953, 52.576) -> (61.9953, 29.5757)
  line L3 (56.7953, 52.576) -> (61.9953, 52.576)
  line L4 (46.7953, 52.576) -> (53.5953, 52.576)
  line L5 (38.7953, 52.576) -> (43.5953, 52.576)
  line L6 (4.0953, 52.576) -> (35.5953, 52.576)
  line L7 (4.059, 52.3911) -> (4.0953, 52.576)
  curve K1 (4.0953, 52.2766) -> (3.0892, 47.3482)
  curve K2 (3.8984, 24.3042) -> (3.0892, 47.3482)
  line L8 (3.8984, 23.0478) -> (3.8984, 24.3042)
  line L9 (16.7395, 23.0478) -> (3.8984, 23.0478)
  curve K3 (16.7395, 23.0478) -> (16.7893, 22.9942)
  line L10 (16.7893, 23.5776) -> (16.7893, 22.9942)
  line L11 (16.7893, 23.8829) -> (16.7893, 23.5776)
  line L12 (16.7893, 29.5757) -> (16.7893, 23.8829)
  line L13 (3.8984, 23.1542) -> (3.8984, 23.148)
  line L14 (3.8984, 24.3042) -> (3.8984, 23.1542)
  curve K4 (3.1442, 47.6407) -> (3.8984, 24.3042)
  curve K5 (3.0892, 47.3482) -> (3.1442, 47.6407)
  curve K6 (4.0953, 52.2766) -> (3.0892, 47.3482)
  line L15 (4.0953, 51.5145) -> (4.0953, 52.2766)
  line L16 (-2.1063, 24.9915) -> (4.0953, 51.5145)
  curve K7 (-2.1063, 24.9915) -> (-1.6768, 22.7521)
  curve K8 (-0.7116, 21.1775) -> (-1.6768, 22.7521)
  curve K9 (0.7953, 22.4378) -> (-0.7116, 21.1775)
  curve K10 (1.3944, 22.9702) -> (0.7953, 22.4378)
  line L17 (3.8984, 23.148) -> (1.3944, 22.9702)
  closed curve K11 centre (55.1953, 48.3934)
  closed curve K12 centre (45.1953, 48.3934)
  closed curve K13 centre (37.1953, 48.3934)
  closed curve K14 centre (-9.6887, 47.5791)
extrude "Extrude42" add sketch "Sketch41" profile of K2 L8 L13 L14 K4 L16 K7 K8 K9 K10 L17 against normal blind 1
extrude "Extrude43" cut of existing geometry blind 1
extrude "Extrude44" add of existing geometry blind 0.5
delete_face "DeleteFace8"
fillet "Fillet23" radius 1.5
fillet "Fillet24" radius 3
sketch "Sketch42" plane through (0, 36.6701, 0) normal (0, 1, 0) x axis (-1, 0, 0)
  line L1 (58.5, -4.7729) -> (44.5, -4.7729)
  line L2 (58.5, 61.9953) -> (58.5, -4.7729)
  line L3 (44.5, 63.9953) -> (54.5, 63.9953)
  line L4 (44.5, 26.2258) -> (44.5, 63.9953)
  line L5 (44.5, 6.2919) -> (44.5, 26.2258)
  line L6 (44.5, -4.7729) -> (44.5, 6.2919)
  arc A1 centre (64.0366, 78.0685) radius 17 clockwise from (58.5, 61.9953) to (54.5, 63.9953)
  circle C1 centre (94.5, 9.5953) radius 29.45
  circle C2 centre (94.561, 12.7158) radius 38.034
extrude "Extrude45" cut sketch "Sketch42" profile of L2 C2 against normal blind 2
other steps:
joint_origin "JointOrigin1" sketch "Sketch8"

design "Fan BFB1012 97x94x33"
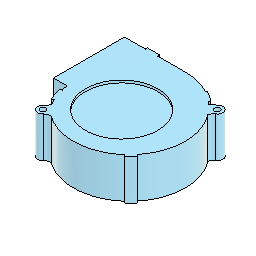
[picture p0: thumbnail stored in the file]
description: STEP AP242
part number: Part 1
base_feature "Base Feature"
